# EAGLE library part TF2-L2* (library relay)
SMALL POLARIZED RELAY WITH HIGH SENSITIVITY NAiS 2 coil latching Source: http://www.mew-europe.com/.. en_ds_61017_0000.pdf
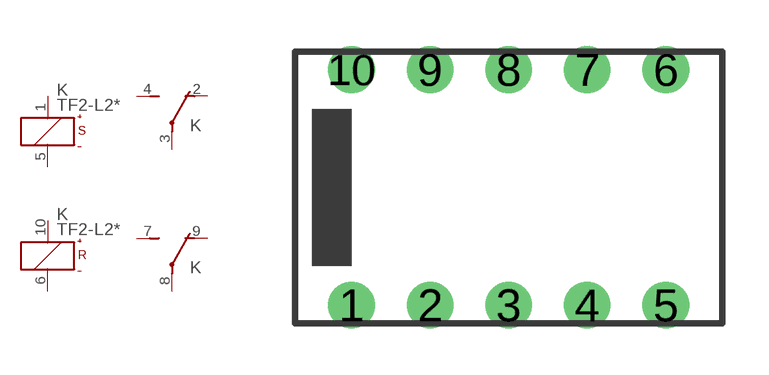
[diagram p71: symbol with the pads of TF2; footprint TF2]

Designator prefix K; gates S=K+-S R=K+-R 1=U 2=U

## TF2-L2-3V (OC_FARNELL: unknown; OC_NEWARK: unknown), TF2-L2-4.5V (OC_FARNELL: unknown; OC_NEWARK: unknown), TF2-L2-5V (OC_FARNELL: unknown; OC_NEWARK: unknown), TF2-L2-6V (OC_FARNELL: unknown; OC_NEWARK: unknown), TF2-L2-9V (OC_FARNELL: unknown; OC_NEWARK: unknown), TF2-L2-12V (OC_FARNELL: unknown; OC_NEWARK: unknown), TF2-L2-24V (OC_FARNELL: unknown; OC_NEWARK: unknown)  [TF2]
1  S:+  pas
2  1:O  pas
3  1:P  pas
4  1:S  pas
5  S:-  pas
6  R:-  pas
7  2:S  pas
8  2:P  pas
9  2:O  pas
10  R:+  pas

## Footprint TF2 (pad centres in mm)
SMALL POLARIZED RELAY WITH HIGH SENSITIVITY NAiS Source: http://www.mew-europe.com/.. en_ds_61017_0000.pdf
drill 1 round: 1 -5.08,-3.81; 2 -2.54,-3.81; 3 0,-3.81; 4 2.54,-3.81; 5 5.08,-3.81; 6 5.08,3.81; 7 2.54,3.81; 8 0,3.81; 9 -2.54,3.81; 10 -5.08,3.81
